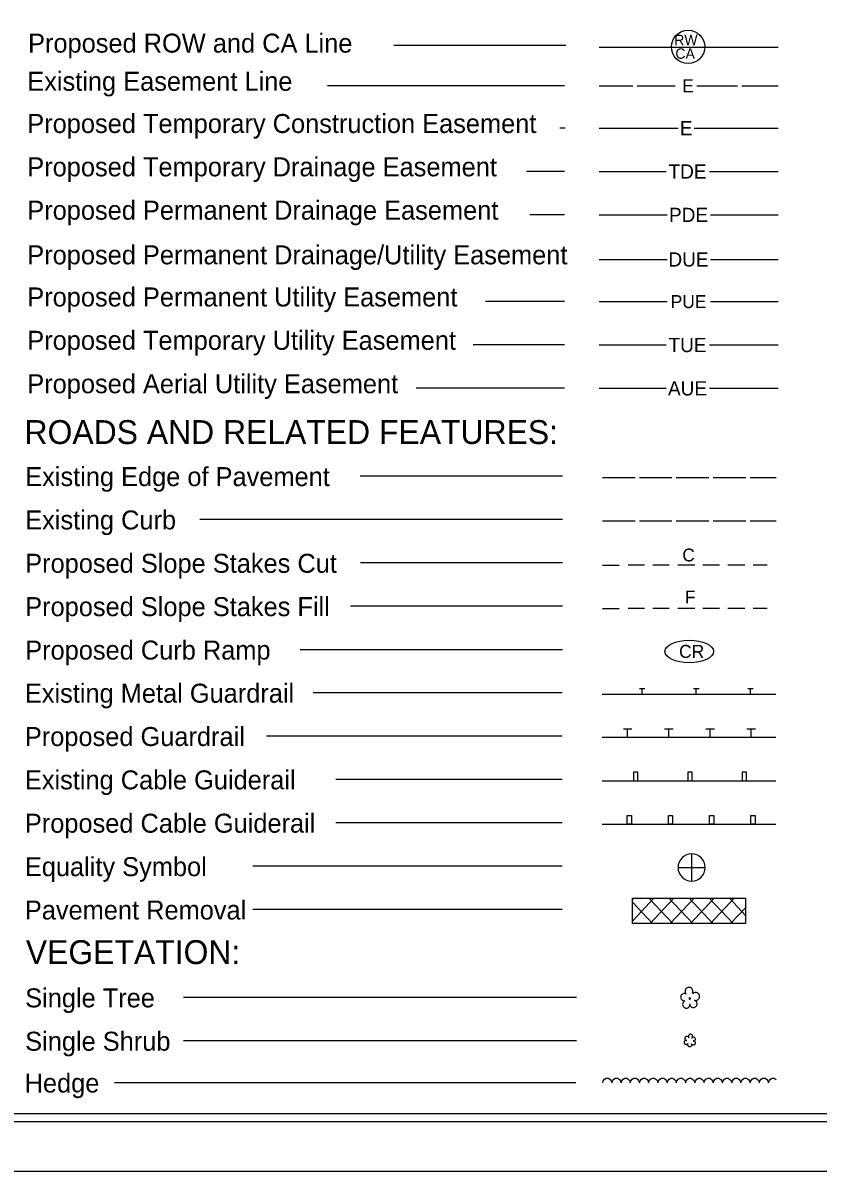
# Model space of a CAD drawing. Extents: x 2594871.4 to 2594905.1, y 784137.6 to 784159.6.
# Drawn here: x 2594882.63 to 2594889.82, y 784137.56 to 784147.95 of the extents above; entities that cross this region are included whole.
import ezdxf

# ---------------------------------------------------------------- set-up
doc = ezdxf.new("R2010")
doc.units = 0
for name, color, linetype in [('Default', 7, 'Continuous'), ('Sheet Plot Border Inside CELL', 7, 'Continuous'), ('Sheet Plot Border Outside CELL', 7, 'Continuous'), ('Sheet Symbology CELL', 7, 'Continuous')]:
    doc.layers.add(name, color=color, linetype=linetype)

msp = doc.modelspace()

# ---------------------------------------------------------------- linework, layer by layer
at = {"layer": 'Default'}
for p, q in [((2594887.537, 784147.742), (2594885.98, 784147.742)), ((2594887.839, 784147.727), (2594889.457, 784147.727)), ((2594887.525, 784147.377), (2594885.382, 784147.377)), ((2594887.839, 784147.377), (2594888.143, 784147.377)), ((2594888.183, 784147.377), (2594888.526, 784147.377)), ((2594888.722, 784147.377), (2594889.09, 784147.377)), ((2594889.129, 784147.377), (2594889.457, 784147.377)), ((2594887.532, 784146.996), (2594887.483, 784146.996)), ((2594887.839, 784146.996), (2594887.89, 784146.996)), ((2594887.89, 784146.996), (2594888.552, 784146.996)), ((2594888.699, 784146.996), (2594889.361, 784146.996)), ((2594889.361, 784146.996), (2594889.457, 784146.996)), ((2594887.525, 784146.603), (2594887.181, 784146.603)), ((2594887.839, 784146.603), (2594887.905, 784146.603)), ((2594887.905, 784146.603), (2594888.444, 784146.603)), ((2594888.836, 784146.603), (2594889.376, 784146.603)), ((2594889.376, 784146.603), (2594889.457, 784146.603)), ((2594887.525, 784146.211), (2594887.211, 784146.211)), ((2594887.839, 784146.211), (2594887.914, 784146.211)), ((2594887.914, 784146.211), (2594888.453, 784146.211)), ((2594888.845, 784146.211), (2594889.385, 784146.211)), ((2594889.385, 784146.211), (2594889.457, 784146.211)), ((2594887.839, 784145.807), (2594888.453, 784145.807)), ((2594888.845, 784145.807), (2594889.457, 784145.807)), ((2594887.525, 784145.426), (2594886.81, 784145.426)), ((2594887.839, 784145.426), (2594887.914, 784145.426)), ((2594887.914, 784145.426), (2594888.454, 784145.426)), ((2594888.846, 784145.426), (2594889.385, 784145.426)), ((2594889.385, 784145.426), (2594889.457, 784145.426)), ((2594887.525, 784145.034), (2594886.698, 784145.034)), ((2594887.839, 784145.034), (2594887.905, 784145.034)), ((2594887.905, 784145.034), (2594888.444, 784145.034)), ((2594888.836, 784145.034), (2594889.376, 784145.034)), ((2594889.376, 784145.034), (2594889.457, 784145.034)), ((2594887.525, 784144.642), (2594886.182, 784144.642)), ((2594887.839, 784144.642), (2594887.905, 784144.642)), ((2594887.905, 784144.642), (2594888.444, 784144.642)), ((2594888.836, 784144.642), (2594889.376, 784144.642)), ((2594889.376, 784144.642), (2594889.457, 784144.642)), ((2594887.506, 784143.847), (2594885.677, 784143.847)), ((2594887.869, 784143.835), (2594888.163, 784143.835)), ((2594888.203, 784143.835), (2594888.497, 784143.835)), ((2594888.536, 784143.835), (2594888.83, 784143.835)), ((2594888.87, 784143.835), (2594889.164, 784143.835)), ((2594889.203, 784143.835), (2594889.438, 784143.835)), ((2594887.506, 784143.454), (2594884.227, 784143.454)), ((2594887.869, 784143.443), (2594888.163, 784143.443)), ((2594888.203, 784143.443), (2594888.497, 784143.443)), ((2594888.536, 784143.443), (2594888.83, 784143.443)), ((2594888.87, 784143.443), (2594889.164, 784143.443)), ((2594889.203, 784143.443), (2594889.438, 784143.443)), ((2594887.506, 784143.062), (2594885.678, 784143.062)), ((2594887.869, 784143.042), (2594888.018, 784143.042)), ((2594888.248, 784143.042), (2594888.1, 784143.042)), ((2594888.473, 784143.042), (2594888.324, 784143.042)), ((2594888.704, 784143.042), (2594888.551, 784143.042)), ((2594888.928, 784143.042), (2594888.776, 784143.042)), ((2594889.155, 784143.042), (2594889.001, 784143.042)), ((2594889.357, 784143.042), (2594889.231, 784143.042)), ((2594887.506, 784142.67), (2594885.589, 784142.67)), ((2594887.869, 784142.649), (2594888.018, 784142.649)), ((2594888.248, 784142.649), (2594888.1, 784142.649)), ((2594888.473, 784142.649), (2594888.324, 784142.649)), ((2594888.704, 784142.649), (2594888.551, 784142.649)), ((2594888.928, 784142.649), (2594888.776, 784142.649)), ((2594889.155, 784142.649), (2594889.001, 784142.649)), ((2594889.357, 784142.649), (2594889.231, 784142.649)), ((2594887.506, 784142.277), (2594885.134, 784142.277)), ((2594887.503, 784141.888), (2594885.25, 784141.888)), ((2594887.866, 784141.876), (2594889.435, 784141.876)), ((2594888.202, 784141.925), (2594888.251, 784141.925)), ((2594888.227, 784141.876), (2594888.227, 784141.925)), ((2594888.693, 784141.925), (2594888.742, 784141.925)), ((2594888.717, 784141.876), (2594888.717, 784141.925)), ((2594889.183, 784141.925), (2594889.232, 784141.925)), ((2594889.208, 784141.876), (2594889.208, 784141.925)), ((2594888.057, 784141.561), (2594888.135, 784141.561)), ((2594888.096, 784141.484), (2594888.096, 784141.561)), ((2594888.43, 784141.561), (2594888.508, 784141.561)), ((2594888.469, 784141.484), (2594888.469, 784141.561)), ((2594888.802, 784141.561), (2594888.881, 784141.561)), ((2594888.841, 784141.484), (2594888.841, 784141.561)), ((2594889.175, 784141.561), (2594889.253, 784141.561)), ((2594889.214, 784141.484), (2594889.214, 784141.561)), ((2594887.503, 784141.495), (2594884.83, 784141.495)), ((2594889.435, 784141.484), (2594887.866, 784141.484)), ((2594887.503, 784141.103), (2594885.457, 784141.103)), ((2594887.866, 784141.092), (2594889.435, 784141.092)), ((2594887.503, 784140.711), (2594885.457, 784140.711)), ((2594887.866, 784140.699), (2594889.435, 784140.699)), ((2594888.675, 784140.429), (2594888.675, 784140.307)), ((2594887.503, 784140.318), (2594884.705, 784140.318)), ((2594888.552, 784140.307), (2594888.675, 784140.307)), ((2594888.675, 784140.307), (2594888.675, 784140.184)), ((2594888.675, 784140.307), (2594888.797, 784140.307)), ((2594888.14, 784140.03), (2594889.162, 784140.03)), ((2594888.14, 784139.8), (2594888.14, 784140.03)), ((2594888.14, 784140.018), (2594888.151, 784140.03)), ((2594888.14, 784139.823), (2594888.333, 784140.03)), ((2594888.321, 784139.8), (2594888.14, 784139.994)), ((2594888.504, 784139.8), (2594888.288, 784140.03)), ((2594888.3, 784139.8), (2594888.515, 784140.03)), ((2594888.685, 784139.8), (2594888.47, 784140.03)), ((2594888.481, 784139.8), (2594888.698, 784140.03)), ((2594888.867, 784139.8), (2594888.652, 784140.03)), ((2594888.663, 784139.8), (2594888.879, 784140.03)), ((2594889.05, 784139.8), (2594888.833, 784140.03)), ((2594888.846, 784139.8), (2594889.061, 784140.03)), ((2594889.162, 784139.874), (2594889.016, 784140.03)), ((2594889.162, 784140.03), (2594889.162, 784139.8)), ((2594887.503, 784139.926), (2594884.705, 784139.926)), ((2594889.027, 784139.8), (2594889.162, 784139.943)), ((2594889.162, 784139.8), (2594888.14, 784139.8)), ((2594887.632, 784139.131), (2594884.079, 784139.131)), ((2594887.632, 784138.738), (2594884.079, 784138.738)), ((2594887.626, 784138.361), (2594883.454, 784138.361)), ((2594887.87, 784138.361), (2594887.875, 784138.379)), ((2594887.875, 784138.379), (2594887.887, 784138.392)), ((2594887.887, 784138.392), (2594887.903, 784138.401)), ((2594887.903, 784138.401), (2594887.922, 784138.401)), ((2594887.922, 784138.401), (2594887.937, 784138.391)), ((2594887.937, 784138.391), (2594887.948, 784138.378)), ((2594887.948, 784138.378), (2594887.952, 784138.362)), ((2594887.953, 784138.361), (2594887.959, 784138.379)), ((2594887.959, 784138.379), (2594887.971, 784138.392)), ((2594887.971, 784138.392), (2594887.986, 784138.401)), ((2594887.986, 784138.401), (2594888.005, 784138.401)), ((2594888.005, 784138.401), (2594888.021, 784138.391)), ((2594888.021, 784138.391), (2594888.031, 784138.378)), ((2594888.031, 784138.378), (2594888.035, 784138.362)), ((2594888.036, 784138.361), (2594888.042, 784138.379)), ((2594888.042, 784138.379), (2594888.054, 784138.392)), ((2594888.054, 784138.392), (2594888.07, 784138.401)), ((2594888.07, 784138.401), (2594888.088, 784138.401)), ((2594888.088, 784138.401), (2594888.104, 784138.391)), ((2594888.104, 784138.391), (2594888.115, 784138.378)), ((2594888.115, 784138.378), (2594888.119, 784138.362)), ((2594888.12, 784138.361), (2594888.126, 784138.379)), ((2594888.126, 784138.379), (2594888.137, 784138.392)), ((2594888.137, 784138.392), (2594888.153, 784138.401)), ((2594888.153, 784138.401), (2594888.172, 784138.401)), ((2594888.172, 784138.401), (2594888.187, 784138.391)), ((2594888.187, 784138.391), (2594888.198, 784138.378)), ((2594888.198, 784138.378), (2594888.202, 784138.362)), ((2594888.203, 784138.361), (2594888.209, 784138.379)), ((2594888.209, 784138.379), (2594888.221, 784138.392)), ((2594888.221, 784138.392), (2594888.236, 784138.401)), ((2594888.236, 784138.401), (2594888.255, 784138.401)), ((2594888.255, 784138.401), (2594888.271, 784138.391)), ((2594888.271, 784138.391), (2594888.281, 784138.378)), ((2594888.281, 784138.378), (2594888.285, 784138.362)), ((2594888.286, 784138.361), (2594888.292, 784138.379)), ((2594888.292, 784138.379), (2594888.304, 784138.392)), ((2594888.304, 784138.392), (2594888.32, 784138.401)), ((2594888.32, 784138.401), (2594888.338, 784138.401)), ((2594888.338, 784138.401), (2594888.354, 784138.391)), ((2594888.354, 784138.391), (2594888.365, 784138.378)), ((2594888.365, 784138.378), (2594888.369, 784138.362)), ((2594888.37, 784138.361), (2594888.376, 784138.379)), ((2594888.376, 784138.379), (2594888.387, 784138.392)), ((2594888.387, 784138.392), (2594888.403, 784138.401)), ((2594888.403, 784138.401), (2594888.422, 784138.401)), ((2594888.422, 784138.401), (2594888.437, 784138.391)), ((2594888.437, 784138.391), (2594888.448, 784138.378)), ((2594888.448, 784138.378), (2594888.452, 784138.362)), ((2594888.453, 784138.361), (2594888.459, 784138.379)), ((2594888.459, 784138.379), (2594888.471, 784138.392)), ((2594888.471, 784138.392), (2594888.486, 784138.401)), ((2594888.486, 784138.401), (2594888.505, 784138.401)), ((2594888.505, 784138.401), (2594888.521, 784138.391)), ((2594888.521, 784138.391), (2594888.532, 784138.378)), ((2594888.532, 784138.378), (2594888.535, 784138.362)), ((2594888.536, 784138.361), (2594888.542, 784138.379)), ((2594888.542, 784138.379), (2594888.554, 784138.392)), ((2594888.554, 784138.392), (2594888.57, 784138.401)), ((2594888.57, 784138.401), (2594888.588, 784138.401)), ((2594888.588, 784138.401), (2594888.604, 784138.391)), ((2594888.604, 784138.391), (2594888.615, 784138.378)), ((2594888.615, 784138.378), (2594888.619, 784138.362)), ((2594888.62, 784138.361), (2594888.626, 784138.379)), ((2594888.626, 784138.379), (2594888.637, 784138.392)), ((2594888.637, 784138.392), (2594888.653, 784138.401)), ((2594888.653, 784138.401), (2594888.672, 784138.401)), ((2594888.672, 784138.401), (2594888.687, 784138.391)), ((2594888.687, 784138.391), (2594888.698, 784138.378)), ((2594888.698, 784138.378), (2594888.702, 784138.362)), ((2594888.703, 784138.361), (2594888.709, 784138.379)), ((2594888.709, 784138.379), (2594888.721, 784138.392)), ((2594888.721, 784138.392), (2594888.737, 784138.401)), ((2594888.737, 784138.401), (2594888.755, 784138.401)), ((2594888.755, 784138.401), (2594888.771, 784138.391)), ((2594888.771, 784138.391), (2594888.782, 784138.378)), ((2594888.782, 784138.378), (2594888.786, 784138.362)), ((2594888.787, 784138.361), (2594888.792, 784138.379)), ((2594888.792, 784138.379), (2594888.804, 784138.392)), ((2594888.804, 784138.392), (2594888.82, 784138.401)), ((2594888.82, 784138.401), (2594888.839, 784138.401)), ((2594888.839, 784138.401), (2594888.854, 784138.391)), ((2594888.854, 784138.391), (2594888.865, 784138.378)), ((2594888.865, 784138.378), (2594888.869, 784138.362)), ((2594888.87, 784138.361), (2594888.876, 784138.379)), ((2594888.876, 784138.379), (2594888.888, 784138.392)), ((2594888.888, 784138.392), (2594888.903, 784138.401)), ((2594888.903, 784138.401), (2594888.922, 784138.401)), ((2594888.922, 784138.401), (2594888.938, 784138.391)), ((2594888.938, 784138.391), (2594888.948, 784138.378)), ((2594888.948, 784138.378), (2594888.952, 784138.362)), ((2594888.953, 784138.361), (2594888.959, 784138.379)), ((2594888.959, 784138.379), (2594888.971, 784138.392)), ((2594888.971, 784138.392), (2594888.987, 784138.401)), ((2594888.987, 784138.401), (2594889.005, 784138.401)), ((2594889.005, 784138.401), (2594889.021, 784138.391)), ((2594889.021, 784138.391), (2594889.032, 784138.378)), ((2594889.032, 784138.378), (2594889.036, 784138.362)), ((2594889.037, 784138.361), (2594889.043, 784138.379)), ((2594889.043, 784138.379), (2594889.054, 784138.392)), ((2594889.054, 784138.392), (2594889.07, 784138.401)), ((2594889.07, 784138.401), (2594889.089, 784138.401)), ((2594889.089, 784138.401), (2594889.104, 784138.391)), ((2594889.104, 784138.391), (2594889.115, 784138.378)), ((2594889.115, 784138.378), (2594889.119, 784138.362)), ((2594889.12, 784138.361), (2594889.126, 784138.379)), ((2594889.126, 784138.379), (2594889.138, 784138.392)), ((2594889.138, 784138.392), (2594889.153, 784138.401)), ((2594889.153, 784138.401), (2594889.172, 784138.401)), ((2594889.172, 784138.401), (2594889.188, 784138.391)), ((2594889.188, 784138.391), (2594889.198, 784138.378)), ((2594889.198, 784138.378), (2594889.202, 784138.362)), ((2594889.203, 784138.361), (2594889.209, 784138.379)), ((2594889.209, 784138.379), (2594889.221, 784138.392)), ((2594889.221, 784138.392), (2594889.237, 784138.401)), ((2594889.237, 784138.401), (2594889.255, 784138.401)), ((2594889.255, 784138.401), (2594889.271, 784138.391)), ((2594889.271, 784138.391), (2594889.282, 784138.378)), ((2594889.282, 784138.378), (2594889.286, 784138.362)), ((2594889.287, 784138.361), (2594889.293, 784138.379)), ((2594889.293, 784138.379), (2594889.304, 784138.392)), ((2594889.304, 784138.392), (2594889.32, 784138.401)), ((2594889.32, 784138.401), (2594889.339, 784138.401)), ((2594889.339, 784138.401), (2594889.354, 784138.391)), ((2594889.354, 784138.391), (2594889.365, 784138.378)), ((2594889.365, 784138.378), (2594889.369, 784138.362)), ((2594889.37, 784138.361), (2594889.376, 784138.379)), ((2594889.376, 784138.379), (2594889.388, 784138.392)), ((2594889.388, 784138.392), (2594889.403, 784138.401)), ((2594889.403, 784138.401), (2594889.422, 784138.401)), ((2594889.422, 784138.401), (2594889.438, 784138.391)), ((2594889.438, 784138.391), (2594889.439, 784138.39))]:
    msp.add_line(p, q, dxfattribs=at)
for points in [[(2594888.15, 784141.092), (2594888.189, 784141.092), (2594888.189, 784141.17), (2594888.15, 784141.17)], [(2594888.64, 784141.092), (2594888.68, 784141.092), (2594888.68, 784141.17), (2594888.64, 784141.17)], [(2594889.131, 784141.092), (2594889.17, 784141.092), (2594889.17, 784141.17), (2594889.131, 784141.17)], [(2594888.091, 784140.778), (2594888.13, 784140.778), (2594888.13, 784140.699), (2594888.091, 784140.699)], [(2594888.464, 784140.778), (2594888.503, 784140.778), (2594888.503, 784140.699), (2594888.464, 784140.699)], [(2594888.836, 784140.778), (2594888.876, 784140.778), (2594888.876, 784140.699), (2594888.836, 784140.699)], [(2594889.209, 784140.778), (2594889.248, 784140.778), (2594889.248, 784140.699), (2594889.209, 784140.699)]]:
    msp.add_lwpolyline(points, close=True, dxfattribs=at)
for points in [[(2594888.682, 784139.172), (2594888.685, 784139.179), (2594888.686, 784139.186), (2594888.686, 784139.193), (2594888.684, 784139.2), (2594888.68, 784139.207), (2594888.676, 784139.213), (2594888.67, 784139.218), (2594888.664, 784139.221), (2594888.656, 784139.223), (2594888.649, 784139.223), (2594888.642, 784139.223), (2594888.635, 784139.22), (2594888.629, 784139.216), (2594888.623, 784139.211), (2594888.619, 784139.205), (2594888.616, 784139.198), (2594888.615, 784139.191), (2594888.615, 784139.183), (2594888.617, 784139.176), (2594888.62, 784139.169), (2594888.625, 784139.163), (2594888.618, 784139.166), (2594888.612, 784139.168), (2594888.605, 784139.167), (2594888.598, 784139.165), (2594888.591, 784139.162), (2594888.585, 784139.158), (2594888.581, 784139.152), (2594888.578, 784139.146), (2594888.576, 784139.14), (2594888.575, 784139.132), (2594888.576, 784139.125), (2594888.579, 784139.119), (2594888.583, 784139.113), (2594888.588, 784139.108), (2594888.594, 784139.104), (2594888.6, 784139.101), (2594888.607, 784139.101), (2594888.614, 784139.101), (2594888.608, 784139.098), (2594888.602, 784139.093), (2594888.598, 784139.087), (2594888.595, 784139.081), (2594888.594, 784139.074), (2594888.593, 784139.067), (2594888.595, 784139.06), (2594888.598, 784139.053), (2594888.601, 784139.047), (2594888.606, 784139.043), (2594888.612, 784139.039), (2594888.619, 784139.036), (2594888.626, 784139.036), (2594888.633, 784139.036), (2594888.64, 784139.038), (2594888.646, 784139.042), (2594888.652, 784139.047), (2594888.656, 784139.052), (2594888.659, 784139.058), (2594888.66, 784139.065)], [(2594888.658, 784139.074), (2594888.659, 784139.066), (2594888.661, 784139.059), (2594888.665, 784139.053), (2594888.67, 784139.047), (2594888.676, 784139.043), (2594888.683, 784139.041), (2594888.691, 784139.04), (2594888.698, 784139.041), (2594888.705, 784139.043), (2594888.711, 784139.047), (2594888.717, 784139.052), (2594888.721, 784139.058), (2594888.723, 784139.065), (2594888.725, 784139.072), (2594888.724, 784139.08), (2594888.723, 784139.087), (2594888.719, 784139.094), (2594888.714, 784139.099), (2594888.708, 784139.103), (2594888.701, 784139.106), (2594888.709, 784139.105), (2594888.717, 784139.105), (2594888.723, 784139.108), (2594888.73, 784139.111), (2594888.737, 784139.115), (2594888.741, 784139.121), (2594888.745, 784139.128), (2594888.747, 784139.135), (2594888.747, 784139.143), (2594888.746, 784139.151), (2594888.744, 784139.158), (2594888.739, 784139.164), (2594888.734, 784139.169), (2594888.727, 784139.173), (2594888.72, 784139.176), (2594888.713, 784139.177), (2594888.705, 784139.177), (2594888.697, 784139.175), (2594888.691, 784139.171), (2594888.685, 784139.166)], [(2594888.66, 784139.128), (2594888.657, 784139.128), (2594888.654, 784139.128), (2594888.652, 784139.125), (2594888.652, 784139.122), (2594888.652, 784139.119), (2594888.655, 784139.117), (2594888.658, 784139.117), (2594888.661, 784139.118), (2594888.663, 784139.12), (2594888.664, 784139.123), (2594888.662, 784139.126), (2594888.66, 784139.128)], [(2594888.649, 784138.767), (2594888.646, 784138.772), (2594888.642, 784138.775), (2594888.637, 784138.779), (2594888.632, 784138.779), (2594888.626, 784138.779), (2594888.621, 784138.777), (2594888.616, 784138.773), (2594888.613, 784138.769), (2594888.612, 784138.763), (2594888.612, 784138.758), (2594888.613, 784138.752), (2594888.616, 784138.748), (2594888.621, 784138.744), (2594888.626, 784138.741), (2594888.632, 784138.741), (2594888.626, 784138.742), (2594888.621, 784138.742), (2594888.616, 784138.741), (2594888.612, 784138.738), (2594888.608, 784138.734), (2594888.607, 784138.729), (2594888.606, 784138.724), (2594888.607, 784138.718), (2594888.609, 784138.714), (2594888.613, 784138.71), (2594888.618, 784138.708), (2594888.622, 784138.706), (2594888.628, 784138.707), (2594888.632, 784138.708), (2594888.637, 784138.711), (2594888.64, 784138.715), (2594888.638, 784138.71), (2594888.637, 784138.704), (2594888.639, 784138.699), (2594888.641, 784138.694), (2594888.645, 784138.69), (2594888.649, 784138.687), (2594888.655, 784138.686), (2594888.66, 784138.687), (2594888.666, 784138.688), (2594888.67, 784138.691), (2594888.673, 784138.696), (2594888.676, 784138.701), (2594888.676, 784138.707), (2594888.675, 784138.712), (2594888.677, 784138.708), (2594888.682, 784138.704), (2594888.686, 784138.703), (2594888.692, 784138.702), (2594888.697, 784138.703), (2594888.702, 784138.705), (2594888.706, 784138.709), (2594888.708, 784138.714), (2594888.709, 784138.719), (2594888.709, 784138.724), (2594888.707, 784138.729), (2594888.703, 784138.733), (2594888.7, 784138.736), (2594888.694, 784138.738), (2594888.689, 784138.738), (2594888.694, 784138.738), (2594888.7, 784138.74), (2594888.703, 784138.743), (2594888.707, 784138.748), (2594888.709, 784138.752), (2594888.709, 784138.758), (2594888.708, 784138.763), (2594888.705, 784138.768), (2594888.701, 784138.771), (2594888.696, 784138.773), (2594888.69, 784138.774), (2594888.686, 784138.772), (2594888.68, 784138.77), (2594888.677, 784138.766), (2594888.675, 784138.762)], [(2594888.673, 784138.762), (2594888.677, 784138.764), (2594888.681, 784138.769), (2594888.683, 784138.773), (2594888.684, 784138.779), (2594888.684, 784138.784), (2594888.682, 784138.789), (2594888.679, 784138.793), (2594888.675, 784138.797), (2594888.669, 784138.799), (2594888.664, 784138.799), (2594888.659, 784138.799), (2594888.654, 784138.796), (2594888.649, 784138.792), (2594888.647, 784138.788), (2594888.645, 784138.782), (2594888.645, 784138.777), (2594888.646, 784138.772), (2594888.649, 784138.767)]]:
    msp.add_lwpolyline(points, dxfattribs=at)
msp.add_circle((2594888.643, 784147.73), 0.151, dxfattribs=at)
for start, end in [(89.9944, 179.9989), (359.9944, 89.9989), (179.9944, 269.9989), (269.9944, 359.9989)]:
    msp.add_arc((2594888.675, 784140.307), 0.123, start, end, dxfattribs=at)
msp.add_ellipse((2594888.653, 784142.261), major_axis=(0.22, 0), ratio=0.462467, dxfattribs=at)
at = {"layer": 'Sheet Plot Border Inside CELL'}
msp.add_lwpolyline([(2594871.632, 784138.011), (2594904.962, 784138.011), (2594904.962, 784159.113), (2594871.632, 784159.113)], close=True, dxfattribs=at)
at = {"layer": 'Sheet Plot Border Outside CELL'}
msp.add_lwpolyline([(2594905.052, 784159.562), (2594871.372, 784159.562), (2594871.372, 784137.562), (2594905.052, 784137.562)], close=True, dxfattribs=at)
at = {"layer": 'Sheet Symbology CELL'}
msp.add_lwpolyline([(2594904.712, 784159.062), (2594874.712, 784159.062), (2594874.712, 784138.082), (2594904.712, 784138.082)], close=True, dxfattribs=at)

# ---------------------------------------------------------------- texts
at = {"layer": 'Default'}
for s, height, p in [('Proposed ROW and CA Line', 0.17164, (2594882.672, 784147.678)), ('RW', 0.0949, (2594888.517, 784147.745)), ('CA', 0.0949, (2594888.528, 784147.622)), ('Existing Easement Line', 0.17164, (2594882.665, 784147.333)), ('E', 0.118, (2594888.589, 784147.318)), ('Proposed Temporary Construction Easement', 0.17164, (2594882.665, 784146.951)), ('E', 0.128, (2594888.569, 784146.931)), ('Proposed Temporary Drainage Easement', 0.17164, (2594882.665, 784146.559)), ('TDE', 0.1285, (2594888.466, 784146.539)), ('Proposed Permanent Drainage Easement', 0.17164, (2594882.665, 784146.167)), ('PDE', 0.1285, (2594888.47, 784146.146)), ('Proposed Permanent Drainage/Utility Easement', 0.17164, (2594882.665, 784145.763)), ('DUE', 0.1285, (2594888.465, 784145.743)), ('Proposed Permanent Utility Easement', 0.17164, (2594882.665, 784145.382)), ('PUE', 0.1177, (2594888.485, 784145.367)), ('Proposed Temporary Utility Easement', 0.17164, (2594882.665, 784144.99)), ('TUE', 0.1285, (2594888.466, 784144.969)), ('Proposed Aerial Utility Easement', 0.17164, (2594882.665, 784144.597)), ('AUE', 0.1285, (2594888.461, 784144.577)), ('ROADS AND RELATED FEATURES:', 0.21577, (2594882.64, 784144.138)), ('Existing Edge of Pavement', 0.17164, (2594882.646, 784143.757)), ('Existing Curb', 0.17164, (2594882.646, 784143.365)), ('C', 0.116, (2594888.591, 784143.076)), ('Proposed Slope Stakes Cut', 0.17164, (2594882.646, 784142.973)), ('F', 0.116, (2594888.615, 784142.696)), ('Proposed Slope Stakes Fill', 0.17164, (2594882.646, 784142.581)), ('Proposed Curb Ramp', 0.17164, (2594882.646, 784142.188)), ('CR', 0.1177, (2594888.561, 784142.203)), ('Existing Metal Guardrail', 0.17164, (2594882.643, 784141.798)), ('Proposed Guardrail', 0.17164, (2594882.643, 784141.406)), ('Existing Cable Guiderail', 0.17164, (2594882.643, 784141.014)), ('Proposed Cable Guiderail', 0.17164, (2594882.643, 784140.622)), ('Equality Symbol', 0.17164, (2594882.643, 784140.229)), ('Pavement Removal', 0.17164, (2594882.643, 784139.837)), ('VEGETATION:', 0.21577, (2594882.652, 784139.434)), ('Single Tree', 0.17164, (2594882.646, 784139.042)), ('Single Shrub', 0.17164, (2594882.646, 784138.65)), ('Hedge', 0.1716, (2594882.641, 784138.272))]:
    msp.add_text(s, height=height, rotation=360, dxfattribs=at).set_placement(p)

doc.saveas('drawing.dxf')
